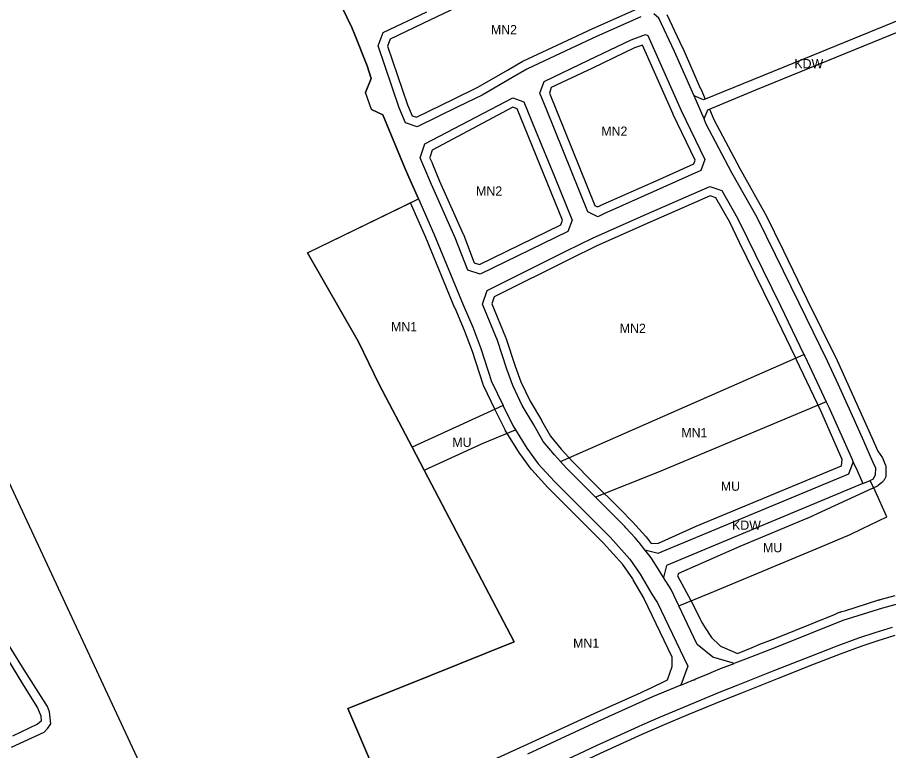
# Model space of a CAD drawing. Extents: x 7435758 to 7439981, y 5550649 to 5554049.
# Drawn here: x 7436617.4 to 7437108.2, y 5551497.9 to 5551911.1 of the extents above; entities that cross this region are included whole.
import ezdxf

# ---------------------------------------------------------------- set-up
doc = ezdxf.new("R2010")
doc.units = 0
for name, color, linetype in [('_Tereny dla których obowiązuje MPZP', 7, 'Continuous'), ('linie_rozgraniczające', 7, 'Continuous'), ('linie_zabudowy_nieprzekraczalne', 7, 'Continuous'), ('oznaczenia_przeznaczen', 7, 'Continuous')]:
    doc.layers.add(name, color=color, linetype=linetype)

msp = doc.modelspace()

# ---------------------------------------------------------------- linework, layer by layer
at = {"layer": '_Tereny dla których obowiązuje MPZP'}
for p, q in [((7436805.8, 5551905.51), (7436800.14, 5551917.03)), ((7436807.49, 5551901.3), (7436805.8, 5551905.51)), ((7436823.3, 5551856.25), (7436816.82, 5551859.18)), ((7436835.56, 5551826.72), (7436823.3, 5551856.25)), ((7436821.23, 5551704.3), (7436809.54, 5551728.26)), ((7436819.25, 5551484.94), (7436803.56, 5551521.54))]:
    msp.add_line(p, q, dxfattribs=at)
for points in [[(7436816.73, 5551876.72), (7436814.47, 5551883.86), (7436807.49, 5551901.3)], [(7436816.82, 5551859.18), (7436813.57, 5551868.83), (7436816.73, 5551876.72)], [(7436838.82, 5551806.63), (7436843.32, 5551808.82), (7436837.92, 5551821.02), (7436835.56, 5551826.72)], [(7436809.54, 5551728.26), (7436780.9, 5551778.49), (7436838.82, 5551806.63)], [(7436574.58, 5551700.76), (7436585.89, 5551706.11), (7436720.07, 5551418.24), (7436733.75, 5551423.85)], [(7436897.23, 5551559.22), (7436846.57, 5551655.92), (7436839.8, 5551668.84), (7436821.23, 5551704.3)], [(7436803.56, 5551521.54), (7436834.79, 5551533.96), (7436897.23, 5551559.22)]]:
    msp.add_lwpolyline(points, dxfattribs=at)
at = {"layer": 'linie_rozgraniczające'}
for p, q in [((7436800.14, 5551917.03), (7436805.8, 5551905.51)), ((7436805.8, 5551905.51), (7436800.14, 5551917.03)), ((7437131.52, 5551916.61), (7437060.3, 5551887.61)), ((7436823.55, 5551902.55), (7436848.07, 5551914.24)), ((7436968.62, 5551911.41), (7436943.64, 5551900.28)), ((7436978.85, 5551910.62), (7436976, 5551913.14)), ((7436987.7, 5551891.81), (7436978.85, 5551910.62)), ((7437033.37, 5551870.27), (7437132.96, 5551910.8)), ((7436805.8, 5551905.51), (7436807.49, 5551901.3)), ((7436807.49, 5551901.3), (7436805.8, 5551905.51)), ((7436807.49, 5551901.3), (7436814.47, 5551883.86)), ((7436820.59, 5551895.04), (7436823.55, 5551902.55)), ((7436943.64, 5551900.28), (7436929.24, 5551893.62)), ((7436963.17, 5551898.46), (7436971.25, 5551901.55)), ((7436971.25, 5551901.55), (7436972.59, 5551900.95)), ((7436972.59, 5551900.95), (7436983.12, 5551877.27)), ((7436939.19, 5551886.99), (7436963.17, 5551898.46)), ((7436832.51, 5551860.14), (7436820.59, 5551895.04)), ((7436929.24, 5551893.62), (7436908.07, 5551883.69)), ((7436997.78, 5551868.89), (7436987.7, 5551891.81)), ((7436914.1, 5551874.97), (7436939.19, 5551886.99)), ((7437060.3, 5551887.61), (7437003.93, 5551864.69)), ((7436814.47, 5551883.86), (7436816.73, 5551876.72)), ((7436904.34, 5551881.94), (7436896.06, 5551877.12)), ((7436908.07, 5551883.69), (7436904.34, 5551881.94)), ((7436816.73, 5551876.72), (7436813.57, 5551868.83)), ((7436896.06, 5551877.12), (7436879.23, 5551867.3)), ((7436983.12, 5551877.27), (7436991.4, 5551858.61)), ((7436911.8, 5551868.33), (7436914.1, 5551874.97)), ((7436846.88, 5551839.8), (7436896.55, 5551865.82)), ((7436879.23, 5551867.3), (7436865.64, 5551860.75)), ((7436896.55, 5551865.82), (7436902.82, 5551863.53)), ((7436915.66, 5551858.81), (7436911.8, 5551868.33)), ((7436998.63, 5551866.9), (7436997.78, 5551868.89)), ((7437004.26, 5551853.86), (7436998.63, 5551866.9)), ((7437003.93, 5551864.69), (7436998.63, 5551866.9)), ((7437006.37, 5551859.03), (7437033.37, 5551870.27)), ((7436902.82, 5551863.53), (7436909.39, 5551847.42)), ((7436816.82, 5551859.18), (7436823.3, 5551856.25)), ((7436823.3, 5551856.25), (7436816.82, 5551859.18)), ((7436823.3, 5551856.25), (7436835.56, 5551826.72)), ((7436835.56, 5551826.72), (7436823.3, 5551856.25)), ((7436836, 5551851.72), (7436832.51, 5551860.14)), ((7436865.64, 5551860.75), (7436842.71, 5551849.4)), ((7436938.88, 5551801.5), (7436915.66, 5551858.81)), ((7436991.4, 5551858.61), (7437004.63, 5551831.03)), ((7437004.26, 5551853.86), (7437006.37, 5551859.03)), ((7436842.71, 5551849.4), (7436836, 5551851.72)), ((7437005.34, 5551851.36), (7437004.26, 5551853.86)), ((7437019.99, 5551823.59), (7437005.34, 5551851.36)), ((7436909.39, 5551847.42), (7436919.95, 5551821.49)), ((7436844.36, 5551831.88), (7436846.88, 5551839.8)), ((7436846.42, 5551827.1), (7436844.36, 5551831.88)), ((7436835.56, 5551826.72), (7436837.92, 5551821.02)), ((7436850.66, 5551816.89), (7436846.42, 5551827.1)), ((7437004.63, 5551831.03), (7437002.49, 5551824.88)), ((7437002.49, 5551824.88), (7436981.04, 5551815.18)), ((7437034.14, 5551798.36), (7437019.99, 5551823.59)), ((7436837.92, 5551821.02), (7436843.32, 5551808.82)), ((7436864.03, 5551786.96), (7436850.66, 5551816.89)), ((7436919.95, 5551821.49), (7436929.97, 5551796.91)), ((7436981.04, 5551815.18), (7436947.83, 5551800.44)), ((7436971.87, 5551800.23), (7437007.45, 5551815.89)), ((7437007.45, 5551815.89), (7437014.33, 5551813.62)), ((7437014.33, 5551813.62), (7437023.17, 5551797.98)), ((7436780.9, 5551778.49), (7436843.32, 5551808.82)), ((7436843.32, 5551808.82), (7436852.06, 5551789.07)), ((7436944.43, 5551798.78), (7436938.88, 5551801.5)), ((7436941.79, 5551786.92), (7436971.87, 5551800.23)), ((7436947.83, 5551800.44), (7436944.43, 5551798.78)), ((7437023.17, 5551797.98), (7437028.72, 5551786.51)), ((7437044.46, 5551777.27), (7437034.14, 5551798.36)), ((7436929.97, 5551796.91), (7436927.54, 5551790.54)), ((7436852.06, 5551789.07), (7436868.57, 5551749.17)), ((7436927.54, 5551790.54), (7436878.05, 5551766.39)), ((7436871.28, 5551768.74), (7436864.03, 5551786.96)), ((7436926.35, 5551779.35), (7436941.79, 5551786.92)), ((7437028.72, 5551786.51), (7437037.34, 5551768.88)), ((7436780.9, 5551778.49), (7436809.54, 5551728.26)), ((7436903.06, 5551767.66), (7436926.35, 5551779.35)), ((7437057.78, 5551750.11), (7437044.46, 5551777.27)), ((7436878.05, 5551766.39), (7436871.28, 5551768.74)), ((7436882.05, 5551757.11), (7436903.06, 5551767.66)), ((7437037.34, 5551768.88), (7437047.32, 5551748.47)), ((7436879.38, 5551749.51), (7436882.05, 5551757.11)), ((7436868.57, 5551749.17), (7436874, 5551736.55)), ((7436879.8, 5551748.53), (7436879.38, 5551749.51)), ((7436887.83, 5551729.05), (7436879.8, 5551748.53)), ((7437047.32, 5551748.47), (7437060.55, 5551721.15)), ((7437073.91, 5551717.41), (7437057.78, 5551750.11)), ((7436874, 5551736.55), (7436878.59, 5551724.44)), ((7436893.13, 5551712.87), (7436887.83, 5551729.05)), ((7436809.54, 5551728.26), (7436821.23, 5551704.3)), ((7436821.23, 5551704.3), (7436809.54, 5551728.26)), ((7436878.59, 5551724.44), (7436884.53, 5551705.83)), ((7436923.4, 5551660.79), (7437060.54, 5551721.14)), ((7437060.54, 5551721.14), (7437060.55, 5551721.14)), ((7437060.55, 5551721.15), (7437060.55, 5551721.14)), ((7437060.55, 5551721.14), (7437060.96, 5551720.27)), ((7437060.96, 5551720.27), (7437073.16, 5551694.4)), ((7437079.77, 5551704.39), (7437073.91, 5551717.41)), ((7436896.5, 5551703.72), (7436893.13, 5551712.87)), ((7436821.23, 5551704.3), (7436839.8, 5551668.84)), ((7436884.53, 5551705.83), (7436891.02, 5551692.32)), ((7437088.75, 5551684.44), (7437079.77, 5551704.39)), ((7436901.88, 5551692.46), (7436896.5, 5551703.72)), ((7437073.16, 5551694.4), (7436979.07, 5551654.95)), ((7437073.16, 5551694.4), (7437074.53, 5551691.49)), ((7436891.02, 5551692.32), (7436839.8, 5551668.84)), ((7436891.02, 5551692.32), (7436891.1, 5551692.16)), ((7436891.1, 5551692.16), (7436896.46, 5551681.18)), ((7436908.33, 5551681.52), (7436901.88, 5551692.46)), ((7437074.53, 5551691.49), (7437087.82, 5551661.62)), ((7437094.25, 5551672.21), (7437088.75, 5551684.44)), ((7436896.46, 5551681.18), (7436898.01, 5551678.68)), ((7436913.63, 5551672.17), (7436908.33, 5551681.52)), ((7436879.91, 5551671.09), (7436898.01, 5551678.68)), ((7436898.01, 5551678.68), (7436904.5, 5551668.25)), ((7436846.57, 5551655.92), (7436879.91, 5551671.09)), ((7436919.95, 5551664.5), (7436913.63, 5551672.17)), ((7437099.45, 5551660.63), (7437094.25, 5551672.21)), ((7436839.8, 5551668.84), (7436846.57, 5551655.92)), ((7436904.5, 5551668.25), (7436910.87, 5551659.49)), ((7436923.4, 5551660.79), (7436919.95, 5551664.5)), ((7436926.67, 5551657.26), (7436923.4, 5551660.79)), ((7437085.84, 5551653.87), (7437088.31, 5551660.53)), ((7437087.82, 5551661.62), (7437087.92, 5551661.39)), ((7437087.92, 5551661.39), (7437088.31, 5551660.53)), ((7437088.31, 5551660.53), (7437090.46, 5551655.79)), ((7437101.07, 5551657), (7437099.45, 5551660.63)), ((7436846.57, 5551655.92), (7436897.23, 5551559.22)), ((7436910.87, 5551659.49), (7436920.02, 5551649.48)), ((7436938.07, 5551645.7), (7436926.67, 5551657.26)), ((7436979.07, 5551654.95), (7436943.06, 5551640.76)), ((7437090.46, 5551655.79), (7437093.78, 5551648.48)), ((7437100.85, 5551653.56), (7437101.11, 5551656.93)), ((7437101.11, 5551656.93), (7437101.07, 5551657)), ((7436978.46, 5551609.25), (7437085.84, 5551653.87)), ((7437093.78, 5551648.48), (7437097.85, 5551650.19)), ((7437097.85, 5551650.19), (7437099.72, 5551650.97)), ((7437100.68, 5551644.24), (7437097.85, 5551650.19)), ((7437099.72, 5551650.97), (7437100.85, 5551653.56)), ((7436920.02, 5551649.48), (7436934.54, 5551635.04)), ((7436943.06, 5551640.76), (7436938.07, 5551645.7)), ((7437089.16, 5551646.55), (7436983.06, 5551602.18)), ((7437093.78, 5551648.48), (7437089.16, 5551646.55)), ((7436953.44, 5551630.48), (7436943.06, 5551640.76)), ((7437107.34, 5551629.66), (7437100.68, 5551644.24)), ((7436934.54, 5551635.04), (7436951.34, 5551618.24)), ((7436959.58, 5551624.12), (7436953.44, 5551630.48)), ((7437093.23, 5551622.83), (7437107.34, 5551629.66)), ((7436959.6, 5551624.1), (7436959.58, 5551624.12)), ((7436960.28, 5551623.38), (7436959.6, 5551624.1)), ((7436965.37, 5551617.79), (7436960.28, 5551623.38)), ((7437086.63, 5551619.64), (7437093.23, 5551622.83)), ((7436951.34, 5551618.24), (7436962.5, 5551605.85)), ((7436967.41, 5551615.56), (7436965.37, 5551617.79)), ((7436967.72, 5551615.21), (7436967.41, 5551615.56)), ((7437069.6, 5551612.53), (7437086.63, 5551619.64)), ((7436970.99, 5551611.01), (7436967.72, 5551615.21)), ((7436973.84, 5551607.33), (7436970.99, 5551611.01)), ((7436970.99, 5551611.01), (7436978.46, 5551609.25)), ((7437007.51, 5551586.69), (7437069.6, 5551612.53)), ((7436962.5, 5551605.85), (7436968.31, 5551597.34)), ((7436974.93, 5551605.94), (7436973.84, 5551607.33)), ((7436978.45, 5551600.25), (7436974.93, 5551605.94)), ((7436983.06, 5551602.18), (7436981.47, 5551595.36)), ((7436621.2, 5551543.41), (7436588.35, 5551596.16)), ((7436968.31, 5551597.34), (7436974.77, 5551586.13)), ((7436981.47, 5551595.36), (7436978.45, 5551600.25)), ((7436985.65, 5551588.61), (7436981.47, 5551595.36)), ((7436974.77, 5551586.13), (7436978.12, 5551581.08)), ((7436990.03, 5551579.48), (7436985.65, 5551588.61)), ((7436990.03, 5551579.48), (7437007.51, 5551586.69)), ((7436978.12, 5551581.08), (7436984.26, 5551568.21)), ((7436994.96, 5551569.19), (7436990.03, 5551579.48)), ((7437104.79, 5551578.17), (7437082.49, 5551571.18)), ((7437113.83, 5551580.57), (7437104.79, 5551578.17)), ((7436984.26, 5551568.21), (7436995.06, 5551545.39)), ((7437000.48, 5551557.66), (7436994.96, 5551569.19)), ((7437082.49, 5551571.18), (7437045.16, 5551556.09)), ((7437100.72, 5551564.52), (7437110.46, 5551567.5)), ((7437091.55, 5551561.49), (7437100.72, 5551564.52)), ((7436897.23, 5551559.22), (7436834.79, 5551533.96)), ((7437009.3, 5551550.61), (7437000.48, 5551557.66)), ((7437064.45, 5551551.19), (7437079.18, 5551556.96)), ((7437079.18, 5551556.96), (7437091.55, 5551561.49)), ((7437045.16, 5551556.09), (7437027.68, 5551549.46)), ((7436610.73, 5551551.38), (7436620.92, 5551534.56)), ((7437020.18, 5551547.38), (7437009.3, 5551550.61)), ((7437018.27, 5551545.9), (7437021.33, 5551547.05)), ((7437021.33, 5551547.05), (7437020.18, 5551547.38)), ((7437023.04, 5551547.7), (7437021.33, 5551547.05)), ((7437027.68, 5551549.46), (7437023.04, 5551547.7)), ((7437044.18, 5551543.2), (7437064.45, 5551551.19)), ((7436634.35, 5551522.76), (7436621.2, 5551543.41)), ((7436995.06, 5551545.39), (7436991.25, 5551534.79)), ((7437007.84, 5551541.7), (7437008.24, 5551541.87)), ((7437008.24, 5551541.87), (7437014.42, 5551544.44)), ((7437014.42, 5551544.44), (7437018.27, 5551545.9)), ((7437023.43, 5551534.98), (7437044.18, 5551543.2)), ((7436994.85, 5551536.29), (7436998.34, 5551537.74)), ((7436998.34, 5551537.74), (7436998.62, 5551537.86)), ((7436998.62, 5551537.86), (7436999.58, 5551538.26)), ((7436999.58, 5551538.26), (7437007.57, 5551541.59)), ((7437007.57, 5551541.59), (7437007.84, 5551541.7)), ((7436620.92, 5551534.56), (7436628.68, 5551521.98)), ((7436834.79, 5551533.96), (7436803.56, 5551521.54)), ((7436991.25, 5551534.79), (7436975.24, 5551528.13)), ((7436991.25, 5551534.79), (7436994.85, 5551536.29)), ((7437012.97, 5551530.78), (7437023.43, 5551534.98)), ((7436975.24, 5551528.13), (7436944.46, 5551514.32)), ((7436993.26, 5551522.6), (7437012.97, 5551530.78)), ((7436635.53, 5551519.76), (7436634.35, 5551522.76)), ((7436979.75, 5551516.99), (7436993.26, 5551522.6)), ((7436628.68, 5551521.98), (7436630.64, 5551517.54)), ((7436630.64, 5551517.54), (7436630.77, 5551514.46)), ((7436636.34, 5551512.91), (7436635.53, 5551519.76)), ((7436803.56, 5551521.54), (7436819.25, 5551484.94)), ((7436819.25, 5551484.94), (7436803.56, 5551521.54)), ((7436628.7, 5551512.83), (7436614.59, 5551505.95)), ((7436630.77, 5551514.46), (7436628.7, 5551512.83)), ((7436634.58, 5551510.45), (7436636.34, 5551512.91)), ((7436944.46, 5551514.32), (7436904.86, 5551495.96)), ((7436967.25, 5551511.44), (7436969.84, 5551512.59)), ((7436969.84, 5551512.59), (7436979.75, 5551516.99)), ((7436614.1, 5551499.83), (7436632.56, 5551508.26)), ((7436632.56, 5551508.26), (7436634.58, 5551510.45)), ((7436943.73, 5551500.73), (7436967.25, 5551511.44)), ((7436927.29, 5551493.04), (7436943.73, 5551500.73))]:
    msp.add_line(p, q, dxfattribs=at)
for points in [[(7436816.73, 5551876.72), (7436814.47, 5551883.86), (7436807.49, 5551901.3)], [(7436816.82, 5551859.18), (7436813.57, 5551868.83), (7436816.73, 5551876.72)], [(7436838.82, 5551806.63), (7436843.32, 5551808.82), (7436837.92, 5551821.02), (7436835.56, 5551826.72)], [(7436809.54, 5551728.26), (7436780.9, 5551778.49), (7436838.82, 5551806.63)], [(7436574.58, 5551700.76), (7436585.89, 5551706.11), (7436720.07, 5551418.24), (7436733.75, 5551423.85)], [(7436897.23, 5551559.22), (7436846.57, 5551655.92), (7436839.8, 5551668.84), (7436821.23, 5551704.3)], [(7436803.56, 5551521.54), (7436834.79, 5551533.96), (7436897.23, 5551559.22)]]:
    msp.add_lwpolyline(points, dxfattribs=at)
at = {"layer": 'linie_zabudowy_nieprzekraczalne'}
for points in [[(7437113.57, 5551950.23), (7437107.2, 5551959.4), (7437098.81, 5551968.2), (7437094.18, 5551971.93), (7437088.98, 5551975.47), (7437076.64, 5551982.85), (7437076.6, 5551982.87), (7437076.34, 5551983.04), (7437062.06, 5551993.01), (7437053.47, 5551998.85), (7437049.11, 5552001.4), (7437043.18, 5552001.71), (7437026.61, 5551993.87), (7436981.66, 5551972.52), (7436955.24, 5551959.88), (7436949.54, 5551957.15), (7436904.13, 5551935.43), (7436904.12, 5551935.43), (7436904.12, 5551935.43), (7436850.22, 5551909.73), (7436827.48, 5551898.88), (7436825.92, 5551894.92), (7436837.19, 5551861.91), (7436839.78, 5551855.65)], [(7436839.85, 5551855.68), (7436842.36, 5551854.81), (7436863.42, 5551865.24), (7436863.47, 5551865.26), (7436876.88, 5551871.72), (7436893.55, 5551881.44), (7436901.82, 5551886.26), (7436901.94, 5551886.33), (7436902.21, 5551886.46), (7436927.12, 5551898.14), (7436927.14, 5551898.15), (7436941.54, 5551904.82), (7436941.61, 5551904.85), (7436966.58, 5551915.98)], [(7436983.37, 5551912.74), (7436992.22, 5551893.94), (7436992.24, 5551893.91), (7436992.28, 5551893.82), (7437002.36, 5551870.9), (7437002.37, 5551870.87), (7437004.87, 5551865.07)], [(7436944.28, 5551804.42), (7436945.64, 5551804.93), (7436945.73, 5551804.97), (7436945.8, 5551805.01), (7436979, 5551819.74), (7436998.47, 5551828.55), (7436999.23, 5551830.72), (7436986.89, 5551856.45), (7436986.87, 5551856.51), (7436986.83, 5551856.58), (7436978.55, 5551875.24), (7436969.52, 5551895.54), (7436965.14, 5551893.87), (7436941.35, 5551882.48), (7436918.21, 5551871.56), (7436917.14, 5551868.47), (7436942.79, 5551805.15), (7436944.28, 5551804.42)], [(7436849.68, 5551832.18), (7436851.01, 5551829.07), (7436851.03, 5551829.02), (7436855.25, 5551818.87), (7436868.59, 5551789), (7436868.67, 5551788.81), (7436874.8, 5551772.81), (7436877.73, 5551771.8), (7436923.62, 5551794.27), (7436924.6, 5551796.85), (7436899.03, 5551859.59), (7436896.51, 5551860.55), (7436851.02, 5551836.32), (7436849.71, 5551832.19)], [(7437007.31, 5551859.42), (7437009.85, 5551853.53), (7437024.38, 5551825.98), (7437038.5, 5551800.8), (7437038.53, 5551800.75), (7437038.63, 5551800.55), (7437048.95, 5551779.47), (7437062.27, 5551752.32), (7437078.39, 5551719.62), (7437078.45, 5551719.51), (7437078.47, 5551719.46), (7437084.33, 5551706.44), (7437098.81, 5551674.26), (7437098.81, 5551674.26), (7437102.22, 5551666.67), (7437104.72, 5551662.82)], [(7436884.7, 5551749.76), (7436892.45, 5551730.95), (7436892.49, 5551730.85), (7436892.58, 5551730.61), (7436897.85, 5551714.51), (7436901.12, 5551705.67), (7436906.3, 5551694.81), (7436912.64, 5551684.06), (7436912.68, 5551683.99), (7436917.77, 5551675.02), (7436923.72, 5551667.8), (7436930.28, 5551660.72), (7436941.61, 5551649.24), (7436956.96, 5551634.03), (7436957.04, 5551633.95), (7436963.88, 5551626.85), (7436963.91, 5551626.83), (7436963.98, 5551626.75), (7436971.42, 5551618.58), (7436971.56, 5551618.41), (7436971.67, 5551618.28), (7436974.46, 5551614.69), (7436974.53, 5551614.7), (7436978.64, 5551614.86), (7436999.83, 5551624.45), (7437081.72, 5551658.38), (7437082.16, 5551662.03), (7437069.99, 5551689.41), (7437056.44, 5551718.14), (7437056.43, 5551718.15), (7437056.03, 5551719), (7437042.82, 5551746.29), (7437032.85, 5551766.68), (7437024.22, 5551784.31), (7437024.21, 5551784.34), (7437018.74, 5551795.66), (7437010.93, 5551809.48), (7437007.71, 5551810.54), (7436973.88, 5551795.66), (7436943.9, 5551782.39), (7436928.57, 5551774.87), (7436886.09, 5551753.55), (7436884.76, 5551749.74)], [(7436964.42, 5551594.07), (7436964.07, 5551594.68), (7436958.56, 5551602.75), (7436947.71, 5551614.79), (7436931, 5551631.51), (7436916.49, 5551645.93), (7436916.4, 5551646.03), (7436916.33, 5551646.11), (7436907.18, 5551656.12), (7436907.03, 5551656.29), (7436906.83, 5551656.55), (7436906.82, 5551656.55), (7436900.46, 5551665.31), (7436900.26, 5551665.61), (7436892.22, 5551678.53), (7436892.07, 5551678.78), (7436891.97, 5551678.98), (7436886.61, 5551689.97), (7436886.59, 5551690), (7436880.03, 5551703.66), (7436880, 5551703.73), (7436879.87, 5551704.03), (7436879.77, 5551704.31), (7436873.86, 5551722.79), (7436869.36, 5551734.67), (7436863.97, 5551747.19), (7436863.95, 5551747.26), (7436847.46, 5551787.11), (7436838.82, 5551806.63)], [(7437104.72, 5551662.82), (7437106.32, 5551659.22), (7437106.43, 5551658.98), (7437106.53, 5551658.67), (7437106.62, 5551658.36), (7437106.69, 5551658.03), (7437106.73, 5551657.71), (7437106.76, 5551657.38), (7437106.76, 5551657.13), (7437106.72, 5551653.44), (7437106.72, 5551653.37), (7437106.7, 5551653.04), (7437106.66, 5551652.72), (7437106.6, 5551652.4), (7437106.52, 5551652.08), (7437106.42, 5551651.77), (7437106.29, 5551651.46), (7437106.15, 5551651.17), (7437106.04, 5551650.97), (7437105.67, 5551650.34), (7437105.62, 5551650.26), (7437105.44, 5551649.98), (7437105.25, 5551649.72), (7437105.03, 5551649.47), (7437104.8, 5551649.24), (7437104.56, 5551649.02), (7437104.46, 5551648.94), (7437102.3, 5551647.24), (7437102.15, 5551647.12), (7437101.88, 5551646.93), (7437101.59, 5551646.77), (7437101.35, 5551646.64), (7437099.09, 5551645.57), (7437099.05, 5551645.55), (7437099.04, 5551645.55), (7437070.52, 5551632.41), (7437070.45, 5551632.38), (7437062.31, 5551628.77), (7437062.22, 5551628.73), (7437024.51, 5551612.86), (7437024.5, 5551612.86), (7436989.8, 5551597.75), (7436989.35, 5551596.29)], [(7436989.35, 5551596.29), (7436996.74, 5551582.47), (7436999.57, 5551577.06), (7437002.17, 5551571.96)], [(7436968.79, 5551530.71), (7436973.19, 5551532.69), (7436973.32, 5551532.74), (7436983.7, 5551537.74), (7436986.34, 5551545.3), (7436986.31, 5551550.46), (7436970.61, 5551583.36), (7436970.55, 5551583.45), (7436970.44, 5551583.63), (7436964.42, 5551594.07)], [(7437002.17, 5551571.96), (7437002.54, 5551571.22), (7437003.47, 5551569.5), (7437004.01, 5551568.57), (7437004.96, 5551567.05), (7437008.46, 5551561.6), (7437008.48, 5551561.58), (7437008.49, 5551561.57), (7437013.18, 5551557.08), (7437013.3, 5551557.02), (7437013.42, 5551556.96), (7437013.63, 5551556.83), (7437015.73, 5551555.87), (7437023.14, 5551552.64), (7437023.14, 5551552.64), (7437023.16, 5551552.64), (7437031.32, 5551556.05), (7437035.7, 5551557.81), (7437043.14, 5551560.67), (7437043.34, 5551560.75), (7437043.69, 5551560.89), (7437077.82, 5551574.68), (7437079.68, 5551575.44), (7437080.68, 5551575.84), (7437080.69, 5551575.84), (7437080.98, 5551575.95), (7437081.27, 5551576.04), (7437081.83, 5551576.21), (7437083.5, 5551576.74), (7437102.73, 5551582.77), (7437103.3, 5551582.95), (7437103.5, 5551583.01), (7437103.62, 5551583.04), (7437104.3, 5551583.22), (7437111.87, 5551585.22)], [(7437111.79, 5551562.68), (7437102.24, 5551559.75), (7437093.19, 5551556.77), (7437080.95, 5551552.29), (7437066.27, 5551546.54), (7437046.01, 5551538.55), (7437025.28, 5551530.34), (7437014.86, 5551526.15), (7436995.18, 5551517.99), (7436981.72, 5551512.39), (7436969.29, 5551506.88), (7436945.83, 5551496.2), (7436929.42, 5551488.51), (7436914.41, 5551481.41), (7436914.37, 5551481.39), (7436914.35, 5551481.38), (7436902.24, 5551475.82), (7436902.16, 5551475.79), (7436890.43, 5551470.63), (7436890.42, 5551470.63), (7436888.47, 5551466.79), (7436905.69, 5551381.62), (7436905.69, 5551381.59), (7436915.93, 5551329.65)], [(7436827.24, 5551466.3), (7436841.39, 5551472.53), (7436902.77, 5551500.51), (7436942.36, 5551518.85), (7436942.36, 5551518.86), (7436942.42, 5551518.88), (7436968.79, 5551530.71)]]:
    msp.add_lwpolyline(points, dxfattribs=at)

# ---------------------------------------------------------------- texts
at = {"layer": 'oznaczenia_przeznaczen'}
for s, p in [('MN2', (7436884.2, 5551901.61)), ('KDW', (7437055.17, 5551882.44)), ('MN2', (7436946.38, 5551844.39)), ('MN2', (7436875.85, 5551810.65)), ('MN1', (7436827.92, 5551734.21)), ('MN2', (7436956.8, 5551733.29)), ('MN1', (7436991.47, 5551674.5)), ('MU', (7436862.46, 5551669.07)), ('MU', (7437013.75, 5551644.33)), ('KDW', (7437020.07, 5551622.33)), ('MU', (7437037.49, 5551609.66)), ('MN1', (7436930.52, 5551555.84))]:
    msp.add_text(s, height=5.2, dxfattribs=at).set_placement(p)

doc.saveas('drawing.dxf')
